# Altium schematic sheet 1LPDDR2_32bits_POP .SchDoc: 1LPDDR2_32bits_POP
size A3; Date: Not used; ApprovedBy: Not used; CheckedBy: Not used; Author: Not used; CompanyName: STMicroelectronics; DrawnBy: Not used; Engineer: Not used; Organization: Not used; Address1: Not used; Address2: Not used; Address3: Not used; Address4: Not used; DocumentNumber: Not used; Revision: Not used; SheetNumber: 7; SheetTotal: 7
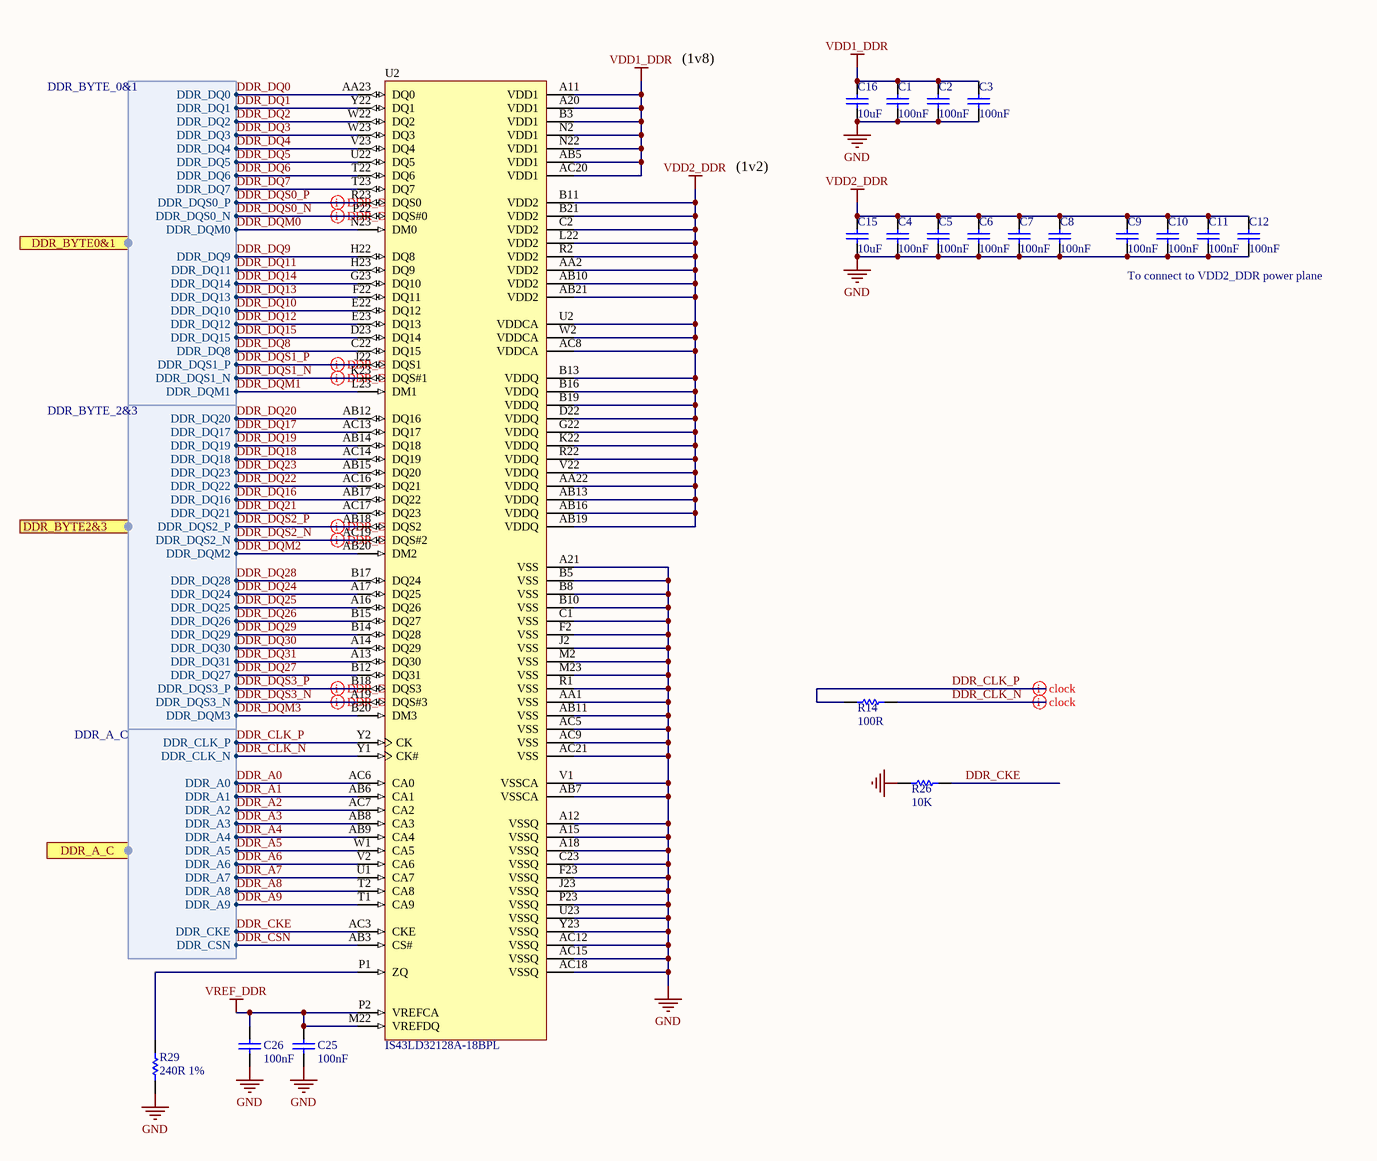
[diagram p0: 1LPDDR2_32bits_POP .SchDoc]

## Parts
C1  value 100nF  [C0402]  (hidden comment: Capacitor)
C2  value 100nF  [C0402]  (hidden comment: Capacitor)
C3  value 100nF  [C0402]  (hidden comment: Capacitor)
C4  value 100nF  [C0402]  (hidden comment: Capacitor)
C5  value 100nF  [C0402]  (hidden comment: Capacitor)
C6  value 100nF  [C0402]  (hidden comment: Capacitor)
C7  value 100nF  [C0402]  (hidden comment: Capacitor)
C8  value 100nF  [C0402]  (hidden comment: Capacitor)
C9  value 100nF  [C0402]  (hidden comment: Capacitor)
C10  value 100nF  [C0402]  (hidden comment: Capacitor)
C11  value 100nF  [C0402]  (hidden comment: Capacitor)
C12  value 100nF  [C0402]  (hidden comment: Capacitor)
C15  value 10uF  [C0603]  (hidden comment: Capacitor)
C16  value 10uF  [C0603]  (hidden comment: Capacitor)
C25  value 100nF  [C0402]  (hidden comment: Capacitor)
C26  value 100nF  [C0402]  (hidden comment: Capacitor)
R14  value 100R  [R0402]  (hidden comment: Resistor)
R26  value 10K  [R0402]  (hidden comment: Resistor)
R29  value 240R 1%  [R0402]  (hidden comment: Resistor)
U2  IS43LD32128A-18BPL  [ICC_FBGA168_12X12_EDB4432BBPA_P050]

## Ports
DDR_A_C (harness DDR_A_C), DDR_BYTE0&1 (harness DDR_BYTE_0&1), DDR_BYTE2&3 (harness DDR_BYTE_2&3)

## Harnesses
DDR_BYTE_0&1: DDR_DQ0, DDR_DQ1, DDR_DQ2, DDR_DQ3, DDR_DQ4, DDR_DQ5, DDR_DQ6, DDR_DQ7, DDR_DQS0_P, DDR_DQS0_N, DDR_DQM0, DDR_DQ9, DDR_DQ11, DDR_DQ14, DDR_DQ13, DDR_DQ10, DDR_DQ12, DDR_DQ15, DDR_DQ8, DDR_DQS1_P, DDR_DQS1_N, DDR_DQM1
DDR_BYTE_2&3: DDR_DQ23, DDR_DQ20, DDR_DQ19, DDR_DQ17, DDR_DQ16, DDR_DQ18, DDR_DQ22, DDR_DQ21, DDR_DQS2_P, DDR_DQS2_N, DDR_DQ25, DDR_DQM2, DDR_DQ28, DDR_DQ29, DDR_DQ24, DDR_DQ26, DDR_DQ30, DDR_DQ31, DDR_DQ27, DDR_DQS3_P, DDR_DQS3_N, DDR_DQM3
DDR_A_C: DDR_CLK_P, DDR_CLK_N, DDR_A0, DDR_A1, DDR_A2, DDR_A3, DDR_A4, DDR_A5, DDR_A6, DDR_A7, DDR_A8, DDR_A9, DDR_CSN, DDR_CKE

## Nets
GND: C1.2 C2.2 C3.2 C4.2 C5.2 C6.2 C7.2 C8.2 C9.2 C10.2 C11.2 C12.2 C15.1 C16.1 C25.2 C26.2 R26.1 R29.1 U2.A12(VSSQ) U2.A15(VSSQ) U2.A18(VSSQ) U2.A21(VSS) U2.AA1(VSS) U2.AB7(VSSCA) U2.AB11(VSS) U2.AC5(VSS) U2.AC9(VSS) U2.AC12(VSSQ) U2.AC15(VSSQ) U2.AC18(VSSQ) U2.AC21(VSS) U2.B5(VSS) U2.B8(VSS) U2.B10(VSS) U2.C1(VSS) U2.C23(VSSQ) U2.F2(VSS) U2.F23(VSSQ) U2.J2(VSS) U2.J23(VSSQ) U2.M2(VSS) U2.M23(VSS) U2.P23(VSSQ) U2.R1(VSS) U2.U23(VSSQ) U2.V1(VSSCA) U2.Y23(VSSQ)
VDD1_DDR: C1.1 C2.1 C3.1 C16.2 U2.A11(VDD1) U2.A20(VDD1) U2.AB5(VDD1) U2.AC20(VDD1) U2.B3(VDD1) U2.N2(VDD1) U2.N22(VDD1)
VDD2_DDR: C4.1 C5.1 C6.1 C7.1 C8.1 C9.1 C10.1 C11.1 C12.1 C15.2 U2.AA2(VDD2) U2.AA22(VDDQ) U2.AB10(VDD2) U2.AB13(VDDQ) U2.AB16(VDDQ) U2.AB19(VDDQ) U2.AB21(VDD2) U2.AC8(VDDCA) U2.B11(VDD2) U2.B13(VDDQ) U2.B16(VDDQ) U2.B19(VDDQ) U2.B21(VDD2) U2.C2(VDD2) U2.D22(VDDQ) U2.G22(VDDQ) U2.K22(VDDQ) U2.L22(VDD2) U2.R2(VDD2) U2.R22(VDDQ) U2.U2(VDDCA) U2.V22(VDDQ) U2.W2(VDDCA)
VREF_DDR: C25.1 C26.1 U2.M22(VREFDQ) U2.P2(VREFCA)
DDR_A0: U2.AC6(CA0) ; port DDR_A_C.DDR_A0
DDR_A1: U2.AB6(CA1) ; port DDR_A_C.DDR_A1
DDR_A2: U2.AC7(CA2) ; port DDR_A_C.DDR_A2
DDR_A3: U2.AB8(CA3) ; port DDR_A_C.DDR_A3
DDR_A4: U2.AB9(CA4) ; port DDR_A_C.DDR_A4
DDR_A5: U2.W1(CA5) ; port DDR_A_C.DDR_A5
DDR_A6: U2.V2(CA6) ; port DDR_A_C.DDR_A6
DDR_A7: U2.U1(CA7) ; port DDR_A_C.DDR_A7
DDR_A8: U2.T2(CA8) ; port DDR_A_C.DDR_A8
DDR_A9: U2.T1(CA9) ; port DDR_A_C.DDR_A9
DDR_CKE: R26.2 U2.AC3(CKE) ; port DDR_A_C.DDR_CKE
DDR_CLK_N: R14.2 U2.Y1(CK#) ; port DDR_A_C.DDR_CLK_N
DDR_CLK_P: R14.1 U2.Y2(CK) ; port DDR_A_C.DDR_CLK_P
DDR_CSN: U2.AB3(CS#) ; port DDR_A_C.DDR_CSN
DDR_DQ0: U2.AA23(DQ0) ; port DDR_BYTE0&1.DDR_DQ0
DDR_DQ1: U2.Y22(DQ1) ; port DDR_BYTE0&1.DDR_DQ1
DDR_DQ2: U2.W22(DQ2) ; port DDR_BYTE0&1.DDR_DQ2
DDR_DQ3: U2.W23(DQ3) ; port DDR_BYTE0&1.DDR_DQ3
DDR_DQ4: U2.V23(DQ4) ; port DDR_BYTE0&1.DDR_DQ4
DDR_DQ5: U2.U22(DQ5) ; port DDR_BYTE0&1.DDR_DQ5
DDR_DQ6: U2.T22(DQ6) ; port DDR_BYTE0&1.DDR_DQ6
DDR_DQ7: U2.T23(DQ7) ; port DDR_BYTE0&1.DDR_DQ7
DDR_DQ8: U2.C22(DQ15) ; port DDR_BYTE0&1.DDR_DQ8
DDR_DQ9: U2.H22(DQ8) ; port DDR_BYTE0&1.DDR_DQ9
DDR_DQ10: U2.E22(DQ12) ; port DDR_BYTE0&1.DDR_DQ10
DDR_DQ11: U2.H23(DQ9) ; port DDR_BYTE0&1.DDR_DQ11
DDR_DQ12: U2.E23(DQ13) ; port DDR_BYTE0&1.DDR_DQ12
DDR_DQ13: U2.F22(DQ11) ; port DDR_BYTE0&1.DDR_DQ13
DDR_DQ14: U2.G23(DQ10) ; port DDR_BYTE0&1.DDR_DQ14
DDR_DQ15: U2.D23(DQ14) ; port DDR_BYTE0&1.DDR_DQ15
DDR_DQ16: U2.AB17(DQ22) ; port DDR_BYTE2&3.DDR_DQ16
DDR_DQ17: U2.AC13(DQ17) ; port DDR_BYTE2&3.DDR_DQ17
DDR_DQ18: U2.AC14(DQ19) ; port DDR_BYTE2&3.DDR_DQ18
DDR_DQ19: U2.AB14(DQ18) ; port DDR_BYTE2&3.DDR_DQ19
DDR_DQ20: U2.AB12(DQ16) ; port DDR_BYTE2&3.DDR_DQ20
DDR_DQ21: U2.AC17(DQ23) ; port DDR_BYTE2&3.DDR_DQ21
DDR_DQ22: U2.AC16(DQ21) ; port DDR_BYTE2&3.DDR_DQ22
DDR_DQ23: U2.AB15(DQ20) ; port DDR_BYTE2&3.DDR_DQ23
DDR_DQ24: U2.A17(DQ25) ; port DDR_BYTE2&3.DDR_DQ24
DDR_DQ25: U2.A16(DQ26) ; port DDR_BYTE2&3.DDR_DQ25
DDR_DQ26: U2.B15(DQ27) ; port DDR_BYTE2&3.DDR_DQ26
DDR_DQ27: U2.B12(DQ31) ; port DDR_BYTE2&3.DDR_DQ27
DDR_DQ28: U2.B17(DQ24) ; port DDR_BYTE2&3.DDR_DQ28
DDR_DQ29: U2.B14(DQ28) ; port DDR_BYTE2&3.DDR_DQ29
DDR_DQ30: U2.A14(DQ29) ; port DDR_BYTE2&3.DDR_DQ30
DDR_DQ31: U2.A13(DQ30) ; port DDR_BYTE2&3.DDR_DQ31
DDR_DQM0: U2.N23(DM0) ; port DDR_BYTE0&1.DDR_DQM0
DDR_DQM1: U2.L23(DM1) ; port DDR_BYTE0&1.DDR_DQM1
DDR_DQM2: U2.AB20(DM2) ; port DDR_BYTE2&3.DDR_DQM2
DDR_DQM3: U2.B20(DM3) ; port DDR_BYTE2&3.DDR_DQM3
DDR_DQS0_N: U2.P22(DQS#0) ; port DDR_BYTE0&1.DDR_DQS0_N
DDR_DQS0_P: U2.R23(DQS0) ; port DDR_BYTE0&1.DDR_DQS0_P
DDR_DQS1_N: U2.K23(DQS#1) ; port DDR_BYTE0&1.DDR_DQS1_N
DDR_DQS1_P: U2.J22(DQS1) ; port DDR_BYTE0&1.DDR_DQS1_P
DDR_DQS2_N: U2.AC19(DQS#2) ; port DDR_BYTE2&3.DDR_DQS2_N
DDR_DQS2_P: U2.AB18(DQS2) ; port DDR_BYTE2&3.DDR_DQS2_P
DDR_DQS3_N: U2.A19(DQS#3) ; port DDR_BYTE2&3.DDR_DQS3_N
DDR_DQS3_P: U2.B18(DQS3) ; port DDR_BYTE2&3.DDR_DQS3_P
NetR29_2: R29.2 U2.P1(ZQ)

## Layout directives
differential pair: DDR_CLK_N, DDR_CLK_P, DDR_DQS0_N, DDR_DQS0_P, DDR_DQS1_N, DDR_DQS1_P, DDR_DQS2_N, DDR_DQS2_P, DDR_DQS3_N, DDR_DQS3_P

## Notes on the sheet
- (1v8)
- (1v2)
- To connect to VDD2_DDR power plane

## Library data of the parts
C1-C12 C25 C26 = MCD-00006: Capacitor, MLCC, 100nF, 16V, X7R, +/-10%, 0402, T=0.5mm; Manufacturer_Part_Number: CC0402KRX7R7BB104; Manufacturer: YAGEO; Alternate_Manufacturer_Part_Number: GCM155R71C104KA55D; Alternate_Manufacturer: MURATA; Provided_By: SUBCO; ECCN_US: EAR99; ECCN_EU: NEC; Order_Code_RS: 616-9701
C15 C16 = MCD-01124: Capacitor, MLCC, 10uF, 10V, X5R, +/-10%, 0603, T=0.8mm; Manufacturer_Part_Number: GRM188R61A106KAAL; Manufacturer: MURATA; Provided_By: SUBCO; ECCN_US: EAR99; ECCN_EU: NEC; Order_Code_RS: 170-6258
R14 = MCD-00067: Resistor,100R,0402,1%,1/16W; Manufacturer_Part_Number: RC0402FR-07100RL; Manufacturer: YAGEO; Provided_By: SUBCO; ECCN_US: EAR99; ECCN_EU: NEC
R26 = MCD-00053: Resistor,10K,0402,1%,1/16W; Manufacturer_Part_Number: RC0402FR-0710KL; Manufacturer: YAGEO; BMS_Part_Number: 9131590; Provided_By: SUBCO; ECCN_US: EAR99; ECCN_EU: NEC
R29 = MCD-00120: Resistor,240R,0402,1%,1/16W; Manufacturer_Part_Number: RC0402FR-07240RL; Manufacturer: YAGEO; ECCN_US: EAR99; ECCN_EU: NEC; Provided_By: SUBCO
U2 = MCD-02089: Memory,LPDDR2,4GB,128Mbx32,533MHz,1066MT/s,1V8,POP-FBGA168; Part_Type: IC; Manufacturer: ISSI; Provided_By: SUBCO; ECCN_EU: NEC; ECCN_US: EAR99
